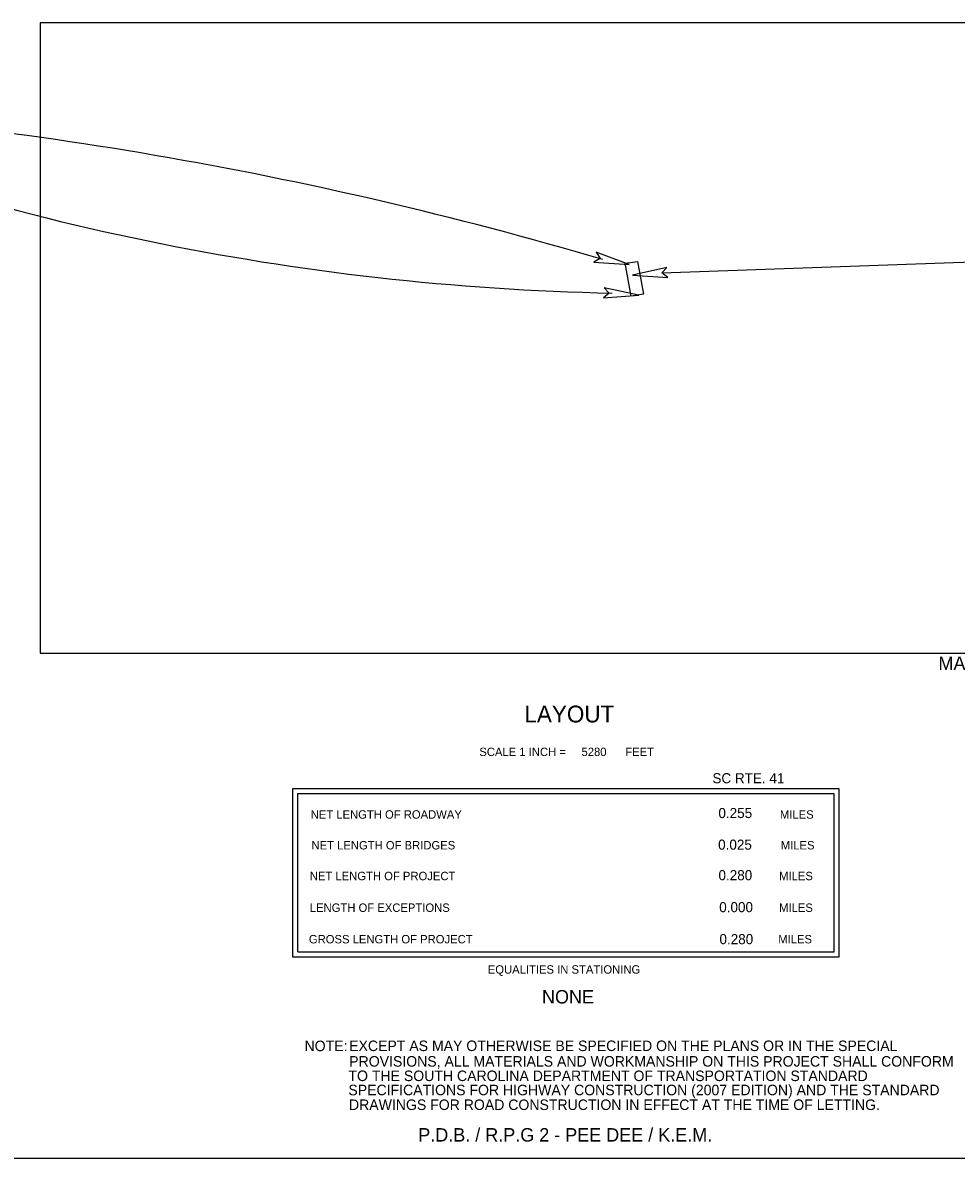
# Model space of a CAD drawing. Extents: x -13615 to 47191, y -1934 to 4415.
# Drawn here: x -11667 to -11112, y 3340 to 4015 of the extents above; entities that cross this region are included whole.
import ezdxf

# ---------------------------------------------------------------- set-up
doc = ezdxf.new("R2010")
doc.units = 0
for name, color, linetype in [('Default', 7, 'Continuous'), ('GN_TitleSheetMap', 7, 'Continuous'), ('RD_SHT_Bndy', 7, 'Continuous'), ('RD_SHT_TX', 7, 'Continuous'), ('RD_TX_TitleSht', 7, 'Continuous')]:
    doc.layers.add(name, color=color, linetype=linetype)

msp = doc.modelspace()

# ---------------------------------------------------------------- linework, layer by layer
at = {"layer": 'Default'}
msp.add_lwpolyline([(-11301.3, 3873.21), (-11297.68, 3853.7), (-11305.08, 3852.46), (-11308.62, 3872.17)], close=True, dxfattribs=at)
at = {"layer": 'GN_TitleSheetMap'}
msp.add_lwpolyline([(-11656.41, 3640.19), (-11031.41, 3640.19), (-11031.41, 4015.19), (-11656.41, 4015.19)], close=True, dxfattribs=at)
at = {"layer": 'RD_SHT_Bndy'}
for p, q in [((-11181.41, 3559.44), (-11506.41, 3559.44)), ((-11506.41, 3559.44), (-11506.41, 3459.44)), ((-11184.36, 3556.44), (-11503.41, 3556.44)), ((-11503.41, 3556.44), (-11503.41, 3462.39)), ((-11184.41, 3462.39), (-11184.41, 3556.44)), ((-11181.41, 3459.44), (-11181.41, 3559.44)), ((-11506.41, 3459.44), (-11181.41, 3459.44)), ((-11503.36, 3462.44), (-11184.36, 3462.44)), ((-12180.51, 3339.59), (-10504.66, 3339.59))]:
    msp.add_line(p, q, dxfattribs=at)
at = {"layer": 'RD_SHT_TX'}
msp.add_line((-11286.76, 3866.39), (-11005.66, 3876.22), dxfattribs=at)
for points in [[(-11306.26, 3871.27), (-11325.93, 3878.61), (-11323.44, 3875), (-11327.2, 3872.75)], [(-11304.28, 3864.94), (-11283.33, 3863.66), (-11286.76, 3866.39), (-11283.82, 3869.64)], [(-11300.59, 3853.18), (-11321.14, 3857.45), (-11318.13, 3854.26), (-11321.51, 3851.47)]]:
    msp.add_lwpolyline(points, close=True, dxfattribs=at)
for centre, radius, start, end in [((-11284.49, 5381.11), 1527.12, 247.86093, 268.8005), ((-11981.48, 1645.35), 2324.41, 73.51732, 87.00403)]:
    msp.add_arc(centre, radius, start, end, dxfattribs=at)

# ---------------------------------------------------------------- texts
for s, height, p in [('MARION COUNTY ', 8, (-11122.35, 3630.05)), ('LAYOUT', 10, (-11368.59, 3598.9)), ('SCALE 1 INCH =     5280      FEET', 5, (-11395.37, 3578.9)), ('NET LENGTH OF ROADWAY', 5.0001, (-11495.66, 3541.64)), ('MILES', 5, (-11216.62, 3541.64)), ('NET LENGTH OF BRIDGES', 5.0001, (-11495.16, 3523.34)), ('MILES', 5, (-11216.12, 3523.34)), ('NET LENGTH OF PROJECT', 5.0001, (-11496.16, 3505.04)), ('MILES', 5, (-11217.12, 3505.04)), ('LENGTH OF EXCEPTIONS', 5.0001, (-11496.16, 3486.19)), ('MILES', 5, (-11217.12, 3486.19)), ('GROSS LENGTH OF PROJECT', 5.0001, (-11496.71, 3467.44)), ('MILES', 5, (-11217.62, 3467.44)), ('EQUALITIES IN STATIONING', 5.0001, (-11390.33, 3449.44)), ('NONE', 8, (-11358.1, 3431.69)), ('NOTE:', 6.25, (-11499.3, 3403.33)), ('EXCEPT AS MAY OTHERWISE BE SPECIFIED ON THE PLANS OR IN THE SPECIAL ', 6.2499, (-11472.76, 3403.39)), ('PROVISIONS, ALL MATERIALS AND WORKMANSHIP ON THIS PROJECT SHALL CONFORM ', 6.2499, (-11472.73, 3394.14)), ('TO THE SOUTH CAROLINA DEPARTMENT OF TRANSPORTATION STANDARD ', 6.2499, (-11473.19, 3385.53)), ('SPECIFICATIONS FOR HIGHWAY CONSTRUCTION (2007 EDITION) AND THE STANDARD', 6.2499, (-11473.23, 3377.1)), ('DRAWINGS FOR ROAD CONSTRUCTION IN EFFECT AT THE TIME OF LETTING.', 6.2499, (-11472.88, 3368.33)), ('P.D.B. / R.P.G 2 - PEE DEE / K.E.M.', 8, (-11431.67, 3349.54))]:
    msp.add_text(s, height=height, dxfattribs=at).set_placement(p)
at = {"layer": 'RD_TX_TitleSht'}
for s, p in [('SC RTE. 41', (-11256.76, 3562.71)), ('0.255', (-11253.21, 3542)), ('0.025', (-11253.38, 3523.19)), ('0.280', (-11253.17, 3505.03)), ('0.000', (-11252.73, 3486.01)), ('0.280', (-11252.59, 3466.98))]:
    msp.add_text(s, height=6, dxfattribs=at).set_placement(p)

doc.saveas('drawing.dxf')
